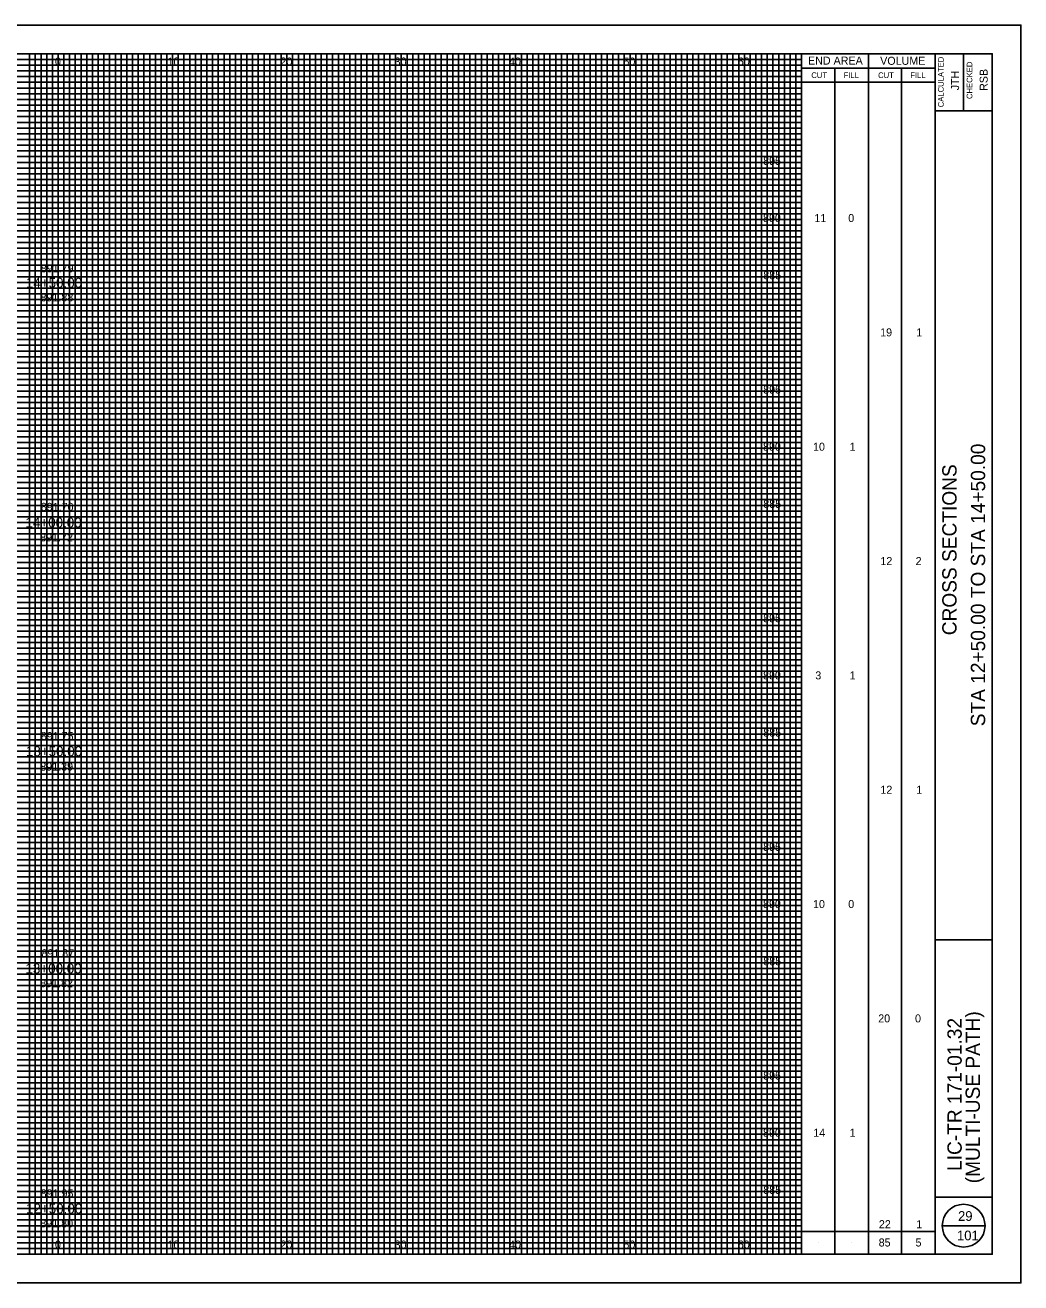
# Model space of a CAD drawing. Extents: x -10 to 160, y -2 to 2522.
# Drawn here: x 72.9 to 160, y 112.5 to 222.5 of the extents above; entities that cross this region are included whole.
import ezdxf

# ---------------------------------------------------------------- set-up
doc = ezdxf.new("R2010")
doc.units = 0
for name, color, linetype in [('GK_Cells', 7, 'Continuous'), ('GK_Patterns', 7, 'Continuous'), ('TX_P_10', 7, 'Continuous'), ('TX_X_10', 7, 'Continuous'), ('XS_P_Finished_Grade_Seeded', 7, 'Continuous'), ('XS_P_Pavt_Surface', 7, 'Continuous'), ('XS_P_Subgrade', 7, 'Continuous'), ('XS_X_Ground_Line', 7, 'Continuous')]:
    doc.layers.add(name, color=color, linetype=linetype)

msp = doc.modelspace()

# ---------------------------------------------------------------- linework, layer by layer
at = {"layer": 'GK_Cells'}
msp.add_lwpolyline([(-10, 112.5), (160, 112.5), (160, 222.5), (-10, 222.5)], close=True, dxfattribs=at)
at = {"layer": 'TX_P_10'}
for p, q in [((140.83, 115), (140.83, 220)), ((146.67, 115), (146.67, 220)), ((140.83, 218.75), (152.5, 218.75)), ((143.75, 115), (143.75, 218.75)), ((149.58, 115), (149.58, 218.75)), ((140.83, 217.5), (152.5, 217.5)), ((140.83, 117), (152.5, 117)), ((153.12, 117.5), (156.88, 117.5)), ((142.29, 116), (142.29, 116)), ((145.21, 116), (145.21, 116)), ((148.12, 116), (148.12, 116)), ((151.04, 116), (151.04, 116))]:
    msp.add_line(p, q, dxfattribs=at)
msp.add_circle((155, 117.5), 1.87, dxfattribs=at)
at = {"layer": 'TX_X_10'}
for p, q in [((75.83, 115), (75.83, 220)), ((80.83, 115), (80.83, 220)), ((85.83, 115), (85.83, 220)), ((90.83, 115), (90.83, 220)), ((95.83, 115), (95.83, 220)), ((100.83, 115), (100.83, 220)), ((105.83, 115), (105.83, 220)), ((110.83, 115), (110.83, 220)), ((115.83, 115), (115.83, 220)), ((120.83, 115), (120.83, 220)), ((125.83, 115), (125.83, 220)), ((130.83, 115), (130.83, 220)), ((135.83, 115), (135.83, 220)), ((5.83, 215), (140.83, 215)), ((5.83, 210), (140.83, 210)), ((5.83, 205), (140.83, 205)), ((5.83, 200), (140.83, 200)), ((5.83, 195), (140.83, 195)), ((5.83, 190), (140.83, 190)), ((5.83, 185), (140.83, 185)), ((5.83, 180), (140.83, 180)), ((5.83, 175), (140.83, 175)), ((5.83, 170), (140.83, 170)), ((5.83, 165), (140.83, 165)), ((5.83, 160), (140.83, 160)), ((5.83, 155), (140.83, 155)), ((5.83, 150), (140.83, 150)), ((5.83, 145), (140.83, 145)), ((5.83, 140), (140.83, 140)), ((5.83, 135), (140.83, 135)), ((5.83, 130), (140.83, 130)), ((5.83, 125), (140.83, 125)), ((5.83, 120), (140.83, 120))]:
    msp.add_line(p, q, dxfattribs=at)
at = {"layer": 'XS_P_Pavt_Surface'}
for p, q in [((152.5, 115), (152.5, 220)), ((155, 220), (155, 215)), ((152.5, 215), (157.5, 215)), ((152.5, 142.5), (157.5, 142.5)), ((152.5, 120), (157.5, 120))]:
    msp.add_line(p, q, dxfattribs=at)
msp.add_lwpolyline([(0, 220), (157.5, 220), (157.5, 115), (0, 115)], close=True, dxfattribs=at)
at = {"layer": 'XS_X_Ground_Line'}
for p, q in [((5.83, 219.5), (140.83, 219.5)), ((5.83, 219), (140.83, 219)), ((73.33, 115), (73.33, 220)), ((73.83, 115), (73.83, 220)), ((74.33, 115), (74.33, 220)), ((74.83, 115), (74.83, 220)), ((75.33, 115), (75.33, 220)), ((76.33, 115), (76.33, 220)), ((76.83, 115), (76.83, 220)), ((77.33, 115), (77.33, 220)), ((77.83, 115), (77.83, 220)), ((78.33, 115), (78.33, 220)), ((78.83, 115), (78.83, 220)), ((79.33, 115), (79.33, 220)), ((79.83, 115), (79.83, 220)), ((80.33, 115), (80.33, 220)), ((81.33, 115), (81.33, 220)), ((81.83, 115), (81.83, 220)), ((82.33, 115), (82.33, 220)), ((82.83, 115), (82.83, 220)), ((83.33, 115), (83.33, 220)), ((83.83, 115), (83.83, 220)), ((84.33, 115), (84.33, 220)), ((84.83, 115), (84.83, 220)), ((85.33, 115), (85.33, 220)), ((86.33, 115), (86.33, 220)), ((86.83, 115), (86.83, 220)), ((87.33, 115), (87.33, 220)), ((87.83, 115), (87.83, 220)), ((88.33, 115), (88.33, 220)), ((88.83, 115), (88.83, 220)), ((89.33, 115), (89.33, 220)), ((89.83, 115), (89.83, 220)), ((90.33, 115), (90.33, 220)), ((91.33, 115), (91.33, 220)), ((91.83, 115), (91.83, 220)), ((92.33, 115), (92.33, 220)), ((92.83, 115), (92.83, 220)), ((93.33, 115), (93.33, 220)), ((93.83, 115), (93.83, 220)), ((94.33, 115), (94.33, 220)), ((94.83, 115), (94.83, 220)), ((95.33, 115), (95.33, 220)), ((96.33, 115), (96.33, 220)), ((96.83, 115), (96.83, 220)), ((97.33, 115), (97.33, 220)), ((97.83, 115), (97.83, 220)), ((98.33, 115), (98.33, 220)), ((98.83, 115), (98.83, 220)), ((99.33, 115), (99.33, 220)), ((99.83, 115), (99.83, 220)), ((100.33, 115), (100.33, 220)), ((101.33, 115), (101.33, 220)), ((101.83, 115), (101.83, 220)), ((102.33, 115), (102.33, 220)), ((102.83, 115), (102.83, 220)), ((103.33, 115), (103.33, 220)), ((103.83, 115), (103.83, 220)), ((104.33, 115), (104.33, 220)), ((104.83, 115), (104.83, 220)), ((105.33, 115), (105.33, 220)), ((106.33, 115), (106.33, 220)), ((106.83, 115), (106.83, 220)), ((107.33, 115), (107.33, 220)), ((107.83, 115), (107.83, 220)), ((108.33, 115), (108.33, 220)), ((108.83, 115), (108.83, 220)), ((109.33, 115), (109.33, 220)), ((109.83, 115), (109.83, 220)), ((110.33, 115), (110.33, 220)), ((111.33, 115), (111.33, 220)), ((111.83, 115), (111.83, 220)), ((112.33, 115), (112.33, 220)), ((112.83, 115), (112.83, 220)), ((113.33, 115), (113.33, 220)), ((113.83, 115), (113.83, 220)), ((114.33, 115), (114.33, 220)), ((114.83, 115), (114.83, 220)), ((115.33, 115), (115.33, 220)), ((116.33, 115), (116.33, 220)), ((116.83, 115), (116.83, 220)), ((117.33, 115), (117.33, 220)), ((117.83, 115), (117.83, 220)), ((118.33, 115), (118.33, 220)), ((118.83, 115), (118.83, 220)), ((119.33, 115), (119.33, 220)), ((119.83, 115), (119.83, 220)), ((120.33, 115), (120.33, 220)), ((121.33, 115), (121.33, 220)), ((121.83, 115), (121.83, 220)), ((122.33, 115), (122.33, 220)), ((122.83, 115), (122.83, 220)), ((123.33, 115), (123.33, 220)), ((123.83, 115), (123.83, 220)), ((124.33, 115), (124.33, 220)), ((124.83, 115), (124.83, 220)), ((125.33, 115), (125.33, 220)), ((126.33, 115), (126.33, 220)), ((126.83, 115), (126.83, 220)), ((127.33, 115), (127.33, 220)), ((127.83, 115), (127.83, 220)), ((128.33, 115), (128.33, 220)), ((128.83, 115), (128.83, 220)), ((129.33, 115), (129.33, 220)), ((129.83, 115), (129.83, 220)), ((130.33, 115), (130.33, 220)), ((131.33, 115), (131.33, 220)), ((131.83, 115), (131.83, 220)), ((132.33, 115), (132.33, 220)), ((132.83, 115), (132.83, 220)), ((133.33, 115), (133.33, 220)), ((133.83, 115), (133.83, 220)), ((134.33, 115), (134.33, 220)), ((134.83, 115), (134.83, 220)), ((135.33, 115), (135.33, 220)), ((136.33, 115), (136.33, 220)), ((136.83, 115), (136.83, 220)), ((137.33, 115), (137.33, 220)), ((137.83, 115), (137.83, 220)), ((138.33, 115), (138.33, 220)), ((138.83, 115), (138.83, 220)), ((139.33, 115), (139.33, 220)), ((139.83, 115), (139.83, 220)), ((140.33, 115), (140.33, 220)), ((5.83, 218.5), (140.83, 218.5)), ((5.83, 218), (140.83, 218)), ((5.83, 217.5), (140.83, 217.5)), ((5.83, 217), (140.83, 217)), ((5.83, 216.5), (140.83, 216.5)), ((5.83, 216), (140.83, 216)), ((5.83, 215.5), (140.83, 215.5)), ((5.83, 214.5), (140.83, 214.5)), ((5.83, 214), (140.83, 214)), ((5.83, 213.5), (140.83, 213.5)), ((5.83, 213), (140.83, 213)), ((5.83, 212.5), (140.83, 212.5)), ((5.83, 212), (140.83, 212)), ((5.83, 211.5), (140.83, 211.5)), ((5.83, 211), (140.83, 211)), ((5.83, 210.5), (140.83, 210.5)), ((5.83, 209.5), (140.83, 209.5)), ((5.83, 209), (140.83, 209)), ((5.83, 208.5), (140.83, 208.5)), ((5.83, 208), (140.83, 208)), ((5.83, 207.5), (140.83, 207.5)), ((5.83, 207), (140.83, 207)), ((5.83, 206.5), (140.83, 206.5)), ((5.83, 206), (140.83, 206)), ((5.83, 205.5), (140.83, 205.5)), ((5.83, 204.5), (140.83, 204.5)), ((5.83, 204), (140.83, 204)), ((5.83, 203.5), (140.83, 203.5)), ((5.83, 203), (140.83, 203)), ((5.83, 202.5), (140.83, 202.5)), ((5.83, 202), (140.83, 202)), ((5.83, 201.5), (140.83, 201.5)), ((5.83, 201), (140.83, 201)), ((5.83, 200.5), (140.83, 200.5)), ((5.83, 199.5), (140.83, 199.5)), ((5.83, 199), (140.83, 199)), ((5.83, 198.5), (140.83, 198.5)), ((5.83, 198), (140.83, 198)), ((5.83, 197.5), (140.83, 197.5)), ((5.83, 197), (140.83, 197)), ((5.83, 196.5), (140.83, 196.5)), ((5.83, 196), (140.83, 196)), ((5.83, 195.5), (140.83, 195.5)), ((5.83, 194.5), (140.83, 194.5)), ((5.83, 194), (140.83, 194)), ((5.83, 193.5), (140.83, 193.5)), ((5.83, 193), (140.83, 193)), ((5.83, 192.5), (140.83, 192.5)), ((5.83, 192), (140.83, 192)), ((5.83, 191.5), (140.83, 191.5)), ((5.83, 191), (140.83, 191)), ((5.83, 190.5), (140.83, 190.5)), ((5.83, 189.5), (140.83, 189.5)), ((5.83, 189), (140.83, 189)), ((5.83, 188.5), (140.83, 188.5)), ((5.83, 188), (140.83, 188)), ((5.83, 187.5), (140.83, 187.5)), ((5.83, 187), (140.83, 187)), ((5.83, 186.5), (140.83, 186.5)), ((5.83, 186), (140.83, 186)), ((5.83, 185.5), (140.83, 185.5)), ((5.83, 184.5), (140.83, 184.5)), ((5.83, 184), (140.83, 184)), ((5.83, 183.5), (140.83, 183.5)), ((5.83, 183), (140.83, 183)), ((5.83, 182.5), (140.83, 182.5)), ((5.83, 182), (140.83, 182)), ((5.83, 181.5), (140.83, 181.5)), ((5.83, 181), (140.83, 181)), ((5.83, 180.5), (140.83, 180.5)), ((5.83, 179.5), (140.83, 179.5)), ((5.83, 179), (140.83, 179)), ((5.83, 178.5), (140.83, 178.5)), ((5.83, 178), (140.83, 178)), ((5.83, 177.5), (140.83, 177.5)), ((5.83, 177), (140.83, 177)), ((5.83, 176.5), (140.83, 176.5)), ((5.83, 176), (140.83, 176)), ((5.83, 175.5), (140.83, 175.5)), ((5.83, 174.5), (140.83, 174.5)), ((5.83, 174), (140.83, 174)), ((5.83, 173.5), (140.83, 173.5)), ((5.83, 173), (140.83, 173)), ((5.83, 172.5), (140.83, 172.5)), ((5.83, 172), (140.83, 172)), ((5.83, 171.5), (140.83, 171.5)), ((5.83, 171), (140.83, 171)), ((5.83, 170.5), (140.83, 170.5)), ((5.83, 169.5), (140.83, 169.5)), ((5.83, 169), (140.83, 169)), ((5.83, 168.5), (140.83, 168.5)), ((5.83, 168), (140.83, 168)), ((5.83, 167.5), (140.83, 167.5)), ((5.83, 167), (140.83, 167)), ((5.83, 166.5), (140.83, 166.5)), ((5.83, 166), (140.83, 166)), ((5.83, 165.5), (140.83, 165.5)), ((5.83, 164.5), (140.83, 164.5)), ((5.83, 164), (140.83, 164)), ((5.83, 163.5), (140.83, 163.5)), ((5.83, 163), (140.83, 163)), ((5.83, 162.5), (140.83, 162.5)), ((5.83, 162), (140.83, 162)), ((5.83, 161.5), (140.83, 161.5)), ((5.83, 161), (140.83, 161)), ((5.83, 160.5), (140.83, 160.5)), ((5.83, 159.5), (140.83, 159.5)), ((5.83, 159), (140.83, 159)), ((5.83, 158.5), (140.83, 158.5)), ((5.83, 158), (140.83, 158)), ((5.83, 157.5), (140.83, 157.5)), ((5.83, 157), (140.83, 157)), ((5.83, 156.5), (140.83, 156.5)), ((5.83, 156), (140.83, 156)), ((5.83, 155.5), (140.83, 155.5)), ((5.83, 154.5), (140.83, 154.5)), ((5.83, 154), (140.83, 154)), ((5.83, 153.5), (140.83, 153.5)), ((5.83, 153), (140.83, 153)), ((5.83, 152.5), (140.83, 152.5)), ((5.83, 152), (140.83, 152)), ((5.83, 151.5), (140.83, 151.5)), ((5.83, 151), (140.83, 151)), ((5.83, 150.5), (140.83, 150.5)), ((5.83, 149.5), (140.83, 149.5)), ((5.83, 149), (140.83, 149)), ((5.83, 148.5), (140.83, 148.5)), ((5.83, 148), (140.83, 148)), ((5.83, 147.5), (140.83, 147.5)), ((5.83, 147), (140.83, 147)), ((5.83, 146.5), (140.83, 146.5)), ((5.83, 146), (140.83, 146)), ((5.83, 145.5), (140.83, 145.5)), ((5.83, 144.5), (140.83, 144.5)), ((5.83, 144), (140.83, 144)), ((5.83, 143.5), (140.83, 143.5)), ((5.83, 143), (140.83, 143)), ((5.83, 142.5), (140.83, 142.5)), ((5.83, 142), (140.83, 142)), ((5.83, 141.5), (140.83, 141.5)), ((5.83, 141), (140.83, 141)), ((5.83, 140.5), (140.83, 140.5)), ((5.83, 139.5), (140.83, 139.5)), ((5.83, 139), (140.83, 139)), ((5.83, 138.5), (140.83, 138.5)), ((5.83, 138), (140.83, 138)), ((5.83, 137.5), (140.83, 137.5)), ((5.83, 137), (140.83, 137)), ((5.83, 136.5), (140.83, 136.5)), ((5.83, 136), (140.83, 136)), ((5.83, 135.5), (140.83, 135.5)), ((5.83, 134.5), (140.83, 134.5)), ((5.83, 134), (140.83, 134)), ((5.83, 133.5), (140.83, 133.5)), ((5.83, 133), (140.83, 133)), ((5.83, 132.5), (140.83, 132.5)), ((5.83, 132), (140.83, 132)), ((5.83, 131.5), (140.83, 131.5)), ((5.83, 131), (140.83, 131)), ((5.83, 130.5), (140.83, 130.5)), ((5.83, 129.5), (140.83, 129.5)), ((5.83, 129), (140.83, 129)), ((5.83, 128.5), (140.83, 128.5)), ((5.83, 128), (140.83, 128)), ((5.83, 127.5), (140.83, 127.5)), ((5.83, 127), (140.83, 127)), ((5.83, 126.5), (140.83, 126.5)), ((5.83, 126), (140.83, 126)), ((5.83, 125.5), (140.83, 125.5)), ((5.83, 124.5), (140.83, 124.5)), ((5.83, 124), (140.83, 124)), ((5.83, 123.5), (140.83, 123.5)), ((5.83, 123), (140.83, 123)), ((5.83, 122.5), (140.83, 122.5)), ((5.83, 122), (140.83, 122)), ((5.83, 121.5), (140.83, 121.5)), ((5.83, 121), (140.83, 121)), ((5.83, 120.5), (140.83, 120.5)), ((5.83, 119.5), (140.83, 119.5)), ((5.83, 119), (140.83, 119)), ((5.83, 118.5), (140.83, 118.5)), ((5.83, 118), (140.83, 118)), ((5.83, 117.5), (140.83, 117.5)), ((5.83, 117), (140.83, 117)), ((5.83, 116.5), (140.83, 116.5)), ((5.83, 116), (140.83, 116)), ((5.83, 115.5), (140.83, 115.5))]:
    msp.add_line(p, q, dxfattribs=at)

# ---------------------------------------------------------------- texts
at = {"layer": 'GK_Patterns'}
for s, height, p in [('0', 0.7, (75.55, 218.97)), ('0', 0.7, (75.55, 218.97)), ('10', 0.7, (85.39, 218.97)), ('20', 0.7, (95.26, 218.97)), ('30', 0.7, (105.25, 218.97)), ('40', 0.7, (115.25, 218.97)), ('50', 0.7, (125.25, 218.97)), ('60', 0.7, (135.25, 218.97)), ('895', 0.7, (137.47, 210.28)), ('890', 0.7, (137.46, 205.28)), ('11', 0.7, (141.95, 205.28)), ('0', 0.7, (144.91, 205.28)), ('14+50.00', 0.875, (73.01, 199.53)), ('885', 0.7, (137.48, 200.28)), ('19', 0.7, (147.7, 195.28)), ('1', 0.7, (150.86, 195.28)), ('895', 0.7, (137.47, 190.28)), ('890', 0.7, (137.46, 185.28)), ('10', 0.7, (141.83, 185.28)), ('1', 0.7, (145.03, 185.28)), ('885', 0.7, (137.48, 180.28)), ('14+00.00', 0.875, (72.97, 178.56)), ('12', 0.7, (147.72, 175.28)), ('2', 0.7, (150.8, 175.28)), ('895', 0.7, (137.47, 170.28)), ('890', 0.7, (137.46, 165.28)), ('3', 0.7, (142.03, 165.28)), ('1', 0.7, (145.03, 165.28)), ('885', 0.7, (137.48, 160.28)), ('13+50.00', 0.875, (73.01, 158.56)), ('12', 0.7, (147.72, 155.28)), ('1', 0.7, (150.86, 155.28)), ('895', 0.7, (137.47, 150.28)), ('890', 0.7, (137.46, 145.28)), ('10', 0.7, (141.83, 145.28)), ('0', 0.7, (144.91, 145.28)), ('885', 0.7, (137.48, 140.28)), ('13+00.00', 0.875, (72.97, 139.56)), ('20', 0.7, (147.53, 135.28)), ('0', 0.7, (150.75, 135.28)), ('895', 0.7, (137.47, 130.28)), ('890', 0.7, (137.46, 125.28)), ('14', 0.7, (141.85, 125.28)), ('1', 0.7, (145.03, 125.28)), ('885', 0.7, (137.48, 120.28)), ('12+50.00', 0.875, (73.02, 118.56)), ('22', 0.7, (147.59, 117.28)), ('1', 0.7, (150.86, 117.28)), ('0', 0.7, (75.55, 115.5)), ('0', 0.7, (75.55, 115.5)), ('10', 0.7, (85.39, 115.5)), ('20', 0.7, (95.26, 115.5)), ('30', 0.7, (105.25, 115.5)), ('40', 0.7, (115.25, 115.5)), ('50', 0.7, (125.25, 115.5)), ('60', 0.7, (135.25, 115.5)), ('85', 0.7, (147.57, 115.68)), ('5', 0.7, (150.79, 115.68))]:
    msp.add_text(s, height=height, dxfattribs=at).set_placement(p)
at = {"layer": 'TX_P_10'}
for s, height, p in [('END AREA', 0.7, (141.39, 219.05)), ('VOLUME', 0.7, (147.7, 219.03)), ('CUT', 0.5, (141.68, 217.87)), ('FILL', 0.5, (144.5, 217.87)), ('CUT', 0.5, (147.52, 217.87)), ('FILL', 0.5, (150.34, 217.87)), ('29', 0.85, (154.51, 117.92)), ('101', 0.85, (154.42, 116.22))]:
    msp.add_text(s, height=height, dxfattribs=at).set_placement(p)
for s, height, p in [('CALCULATED', 0.5, (153.26, 215.32)), ('CHECKED', 0.5, (155.76, 216.04)), ('JTH', 0.7, (154.6, 216.8)), ('RSB', 0.7, (157.1, 216.75)), ('STA 12+50.00 TO STA 14+50.00', 1.25, (156.88, 161.18)), ('CROSS SECTIONS', 1.25, (154.38, 169.14)), ('LIC-TR 171-01.32', 1.25, (154.83, 122.29)), ('(MULTI-USE PATH)', 1.25, (156.42, 121.21))]:
    msp.add_text(s, height=height, rotation=90, dxfattribs=at).set_placement(p)
at = {"layer": 'XS_P_Finished_Grade_Seeded'}
for s, p in [('891.88', (74.29, 198.34)), ('891.72', (74.26, 177.35)), ('891.39', (74.27, 157.3)), ('891.82', (74.26, 138.36)), ('891.80', (74.27, 117.35))]:
    msp.add_text(s, height=0.7, dxfattribs=at).set_placement(p)
at = {"layer": 'XS_P_Subgrade'}
for s, p in [('891.79', (74.31, 200.88)), ('891.70', (74.31, 180.02)), ('891.75', (74.31, 159.97)), ('891.87', (74.36, 140.98)), ('891.95', (74.3, 119.98))]:
    msp.add_text(s, height=0.7, dxfattribs=at).set_placement(p)

doc.saveas('drawing.dxf')
